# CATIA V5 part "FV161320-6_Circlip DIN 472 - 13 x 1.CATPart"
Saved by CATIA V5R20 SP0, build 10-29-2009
Part number: FV161320-6_Circlip DIN 472 - 13 x 1
Revision: ANY
Definition: UNKNOWN
Nomenclature: FV161320-6_Circlip DIN 472 - 13 x 1
Source: Unknown
Bounding box of the stored display mesh (mm): x -6.8 to 6.8, y -6.599 to 6.63, z -1 to 0
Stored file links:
  C:\Users\Utente\Desktop\IO LAVORO\3D X SITO CF\CUMSA\3D files FV\FV 161320\FV161320-6_Circlip DIN 472 - 13 x 1.CATPart
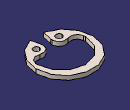
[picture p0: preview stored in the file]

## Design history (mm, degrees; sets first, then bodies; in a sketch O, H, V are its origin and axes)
Body1 "Body" (main body)
  Solid1: solid without history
